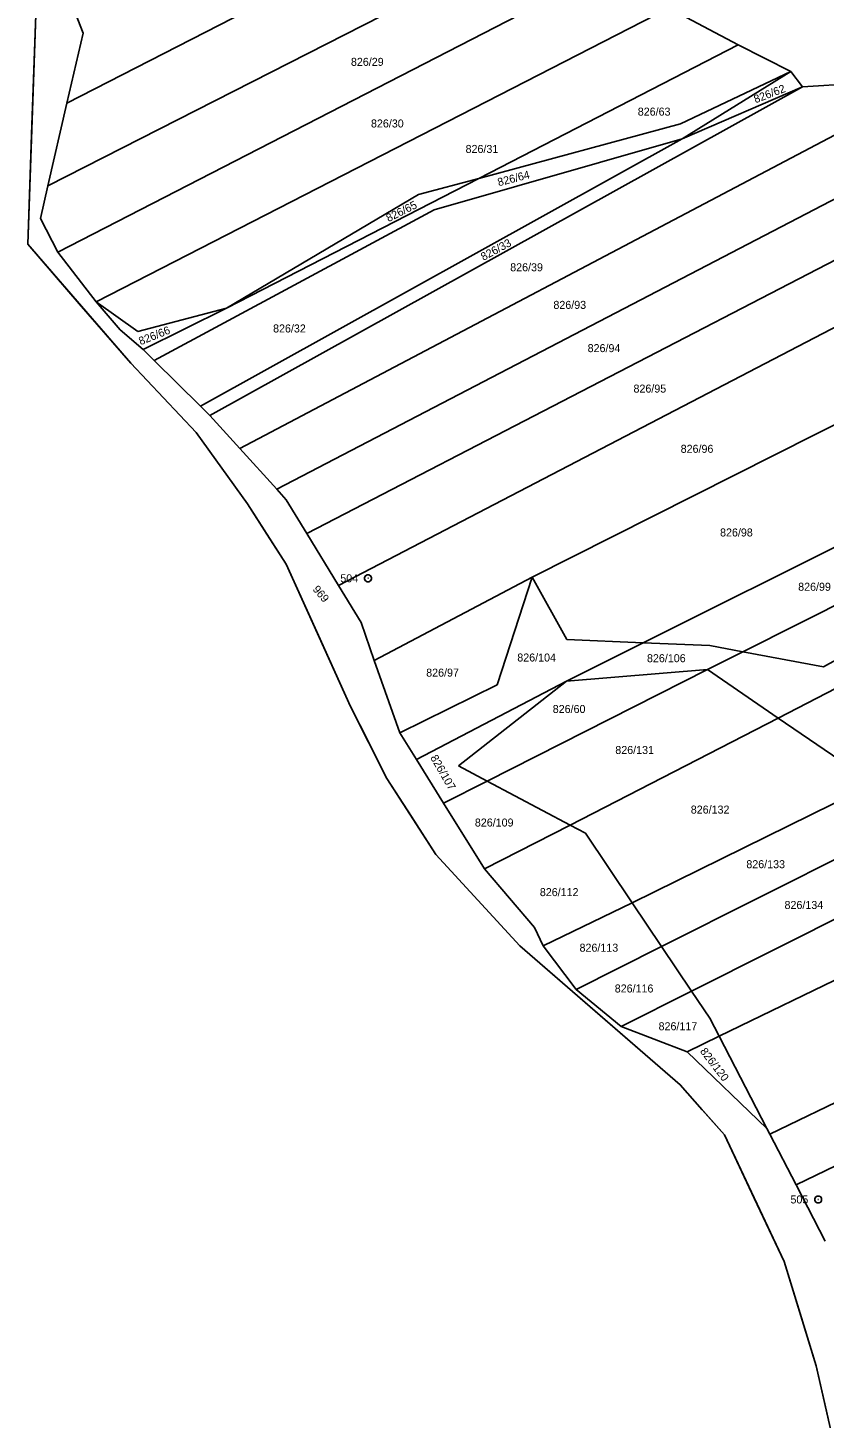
# Model space of a CAD drawing. Extents: x -593358 to -590116, y -1072518 to -1068420.
# Drawn here: x -593005 to -592835.7, y -1070925.3 to -1070630 of the extents above; entities that cross this region are included whole.
import ezdxf

# ---------------------------------------------------------------- set-up
doc = ezdxf.new("R2010")
doc.units = 0
for name, color, linetype in [('katastrální hranice', 7, 'Continuous'), ('Parcela KN', 7, 'Continuous'), ('Parcela ZE', 7, 'Continuous'), ('Parcelní číslo', 7, 'Continuous'), ('vnější obvod_šetřený', 7, 'Continuous'), ('Vrstva 17', 7, 'Continuous'), ('Vrstva 24', 7, 'Continuous')]:
    doc.layers.add(name, color=color, linetype=linetype)

msp = doc.modelspace()

# ---------------------------------------------------------------- linework, layer by layer
at = {"layer": 'katastrální hranice'}
for p, q in [((-593004.98, -1070675.93), (-593003.22, -1070625.24)), ((-592983.1, -1070701.21), (-593004.98, -1070675.93)), ((-592969.21, -1070715.93), (-592983.1, -1070701.21)), ((-592958.26, -1070731.07), (-592969.21, -1070715.93)), ((-592950.09, -1070743.91), (-592958.26, -1070731.07)), ((-592936.37, -1070774.13), (-592950.09, -1070743.91)), ((-592928.69, -1070789.39), (-592936.37, -1070774.13)), ((-592918.25, -1070805.57), (-592928.69, -1070789.39)), ((-592900.4, -1070824.95), (-592918.25, -1070805.57)), ((-592866.35, -1070854.51), (-592900.4, -1070824.95)), ((-592856.92, -1070865.09), (-592866.35, -1070854.51)), ((-592844.25, -1070892), (-592856.92, -1070865.09)), ((-592837.43, -1070914.17), (-592844.25, -1070892)), ((-592832.3, -1070936.59), (-592837.43, -1070914.17))]:
    msp.add_line(p, q, dxfattribs=at)
at = {"layer": 'Parcela KN'}
for p, q in [((-592996.65, -1070645.98), (-592883.74, -1070588.08)), ((-593000.7, -1070663.57), (-592878.48, -1070601.26)), ((-592998.58, -1070677.61), (-592873.65, -1070613.39)), ((-592993.22, -1070631.13), (-592995.33, -1070625.64)), ((-592990.46, -1070688.17), (-592868.72, -1070625.78)), ((-592868.72, -1070625.78), (-592854, -1070633.57)), ((-592993.22, -1070631.13), (-592996.65, -1070645.98)), ((-592854, -1070633.57), (-592909.16, -1070661.95)), ((-592854, -1070633.57), (-592842.82, -1070639.26)), ((-592866.26, -1070650.34), (-592842.82, -1070639.26)), ((-592842.82, -1070639.26), (-592865.95, -1070653.52)), ((-592842.82, -1070639.26), (-592840.32, -1070642.49)), ((-592840.32, -1070642.49), (-592824.4, -1070641.48)), ((-592840.32, -1070642.49), (-592966.27, -1070712.32)), ((-592865.95, -1070653.52), (-592840.32, -1070642.49)), ((-592996.65, -1070645.98), (-593000.7, -1070663.57)), ((-592909.16, -1070661.95), (-592866.26, -1070650.34)), ((-592865.95, -1070653.52), (-592968.26, -1070710.35)), ((-592865.95, -1070653.52), (-592918.61, -1070668.62)), ((-592909.16, -1070661.95), (-592962.78, -1070689.55)), ((-592921.92, -1070665.41), (-592909.16, -1070661.95)), ((-593000.7, -1070663.57), (-593002.29, -1070670.47)), ((-592962.78, -1070689.55), (-592921.92, -1070665.41)), ((-592918.61, -1070668.62), (-592978.11, -1070700.61)), ((-593002.29, -1070670.47), (-592998.58, -1070677.61)), ((-592998.58, -1070677.61), (-592990.46, -1070688.17)), ((-592990.46, -1070688.17), (-592981.59, -1070694.46)), ((-592985.38, -1070694.1), (-592990.46, -1070688.17)), ((-592981.59, -1070694.46), (-592962.78, -1070689.55)), ((-592962.78, -1070689.55), (-592980.43, -1070698.31)), ((-592980.43, -1070698.31), (-592985.38, -1070694.1)), ((-592978.11, -1070700.61), (-592980.43, -1070698.31)), ((-592968.26, -1070710.35), (-592978.11, -1070700.61)), ((-592966.27, -1070712.32), (-592968.26, -1070710.35)), ((-592959.9, -1070719.35), (-592966.27, -1070712.32)), ((-592952.08, -1070727.97), (-592959.9, -1070719.35)), ((-592950.06, -1070730.2), (-592952.08, -1070727.97)), ((-592945.68, -1070737.38), (-592950.06, -1070730.2)), ((-592938.93, -1070748.45), (-592945.68, -1070737.38)), ((-592934.16, -1070756.27), (-592938.93, -1070748.45)), ((-592897.8, -1070746.67), (-592905.23, -1070769.55)), ((-592890.45, -1070759.89), (-592897.8, -1070746.67)), ((-592810.11, -1070751.36), (-592835.85, -1070765.67)), ((-592931.34, -1070764.32), (-592934.16, -1070756.27)), ((-592874.2, -1070760.59), (-592890.45, -1070759.89)), ((-592860.04, -1070761.2), (-592874.2, -1070760.59)), ((-592852.99, -1070762.5), (-592860.04, -1070761.2)), ((-592835.85, -1070765.67), (-592852.99, -1070762.5)), ((-592925.93, -1070779.73), (-592931.34, -1070764.32)), ((-592890.47, -1070768.71), (-592913.44, -1070786.7)), ((-592860.52, -1070766.3), (-592890.47, -1070768.71)), ((-592845.5, -1070776.58), (-592860.52, -1070766.3)), ((-592905.23, -1070769.55), (-592925.93, -1070779.73)), ((-592825.15, -1070790.5), (-592845.5, -1070776.58)), ((-592925.93, -1070779.73), (-592922.4, -1070785.38)), ((-592922.4, -1070785.38), (-592916.62, -1070794.64)), ((-592913.44, -1070786.7), (-592907.33, -1070789.95)), ((-592907.33, -1070789.95), (-592889.75, -1070799.31)), ((-592916.62, -1070794.64), (-592907.89, -1070808.63)), ((-592889.75, -1070799.31), (-592886.47, -1070801.06)), ((-592886.47, -1070801.06), (-592876.55, -1070815.8)), ((-592907.89, -1070808.63), (-592897.29, -1070821.04)), ((-592876.55, -1070815.8), (-592870.28, -1070825.11)), ((-592897.29, -1070821.04), (-592895.46, -1070824.94)), ((-592895.46, -1070824.94), (-592888.41, -1070834.21)), ((-592870.28, -1070825.11), (-592863.9, -1070834.59)), ((-592888.41, -1070834.21), (-592878.89, -1070842.11)), ((-592863.9, -1070834.59), (-592860.04, -1070840.32)), ((-592878.89, -1070842.11), (-592864.83, -1070847.49)), ((-592858.04, -1070844.18), (-592860.04, -1070840.32)), ((-592847.89, -1070863.77), (-592858.04, -1070844.18)), ((-592864.83, -1070847.49), (-592847.89, -1070863.77)), ((-592847.28, -1070864.95), (-592847.89, -1070863.77)), ((-592841.69, -1070875.75), (-592847.28, -1070864.95)), ((-592835.52, -1070887.66), (-592841.69, -1070875.75))]:
    msp.add_line(p, q, dxfattribs=at)
at = {"layer": 'Parcela ZE'}
for p, q in [((-592959.9, -1070719.35), (-592832.17, -1070652.1)), ((-592952.08, -1070727.97), (-592811.32, -1070654.78)), ((-592945.68, -1070737.38), (-592808.7, -1070666.5)), ((-592938.93, -1070748.45), (-592807.39, -1070680.01)), ((-592897.8, -1070746.67), (-592808.2, -1070701.51)), ((-592845.5, -1070776.58), (-592751.39, -1070727.74)), ((-592874.2, -1070760.59), (-592809.23, -1070728.16)), ((-592852.99, -1070762.5), (-592809.7, -1070740.64)), ((-592897.8, -1070746.67), (-592931.34, -1070764.32)), ((-592890.47, -1070768.71), (-592874.2, -1070760.59)), ((-592860.52, -1070766.3), (-592852.99, -1070762.5)), ((-592890.47, -1070768.71), (-592922.4, -1070785.38)), ((-592907.33, -1070789.95), (-592860.52, -1070766.3)), ((-592889.75, -1070799.31), (-592845.5, -1070776.58)), ((-592916.62, -1070794.64), (-592907.33, -1070789.95)), ((-592825.15, -1070790.5), (-592876.55, -1070815.8)), ((-592815.08, -1070797.39), (-592870.28, -1070825.11)), ((-592907.89, -1070808.63), (-592889.75, -1070799.31)), ((-592863.9, -1070834.59), (-592804.37, -1070804.72)), ((-592858.04, -1070844.18), (-592792.97, -1070812.52)), ((-592876.55, -1070815.8), (-592895.46, -1070824.94)), ((-592870.28, -1070825.11), (-592888.41, -1070834.21)), ((-592847.28, -1070864.95), (-592770.39, -1070827.96)), ((-592878.89, -1070842.11), (-592863.9, -1070834.59)), ((-592841.69, -1070875.75), (-592759.25, -1070835.58)), ((-592864.83, -1070847.49), (-592858.04, -1070844.18))]:
    msp.add_line(p, q, dxfattribs=at)
at = {"layer": 'vnější obvod_šetřený'}
for p, q in [((-593003.22, -1070625.24), (-593004.1, -1070650.585)), ((-593004.1, -1070650.585), (-593004.98, -1070675.93)), ((-593004.98, -1070675.93), (-592994.04, -1070688.57)), ((-592994.04, -1070688.57), (-592983.1, -1070701.21)), ((-592983.1, -1070701.21), (-592976.155, -1070708.57)), ((-592976.155, -1070708.57), (-592969.21, -1070715.93)), ((-592969.21, -1070715.93), (-592963.735, -1070723.5)), ((-592963.735, -1070723.5), (-592958.26, -1070731.07)), ((-592958.26, -1070731.07), (-592954.175, -1070737.49)), ((-592954.175, -1070737.49), (-592950.09, -1070743.91)), ((-592950.09, -1070743.91), (-592943.23, -1070759.02)), ((-592943.23, -1070759.02), (-592936.37, -1070774.13)), ((-592936.37, -1070774.13), (-592932.53, -1070781.76)), ((-592932.53, -1070781.76), (-592928.69, -1070789.39)), ((-592928.69, -1070789.39), (-592923.47, -1070797.48)), ((-592923.47, -1070797.48), (-592918.25, -1070805.57)), ((-592918.25, -1070805.57), (-592909.325, -1070815.26)), ((-592909.325, -1070815.26), (-592900.4, -1070824.95)), ((-592900.4, -1070824.95), (-592883.375, -1070839.73)), ((-592883.375, -1070839.73), (-592866.35, -1070854.51)), ((-592866.35, -1070854.51), (-592861.635, -1070859.8)), ((-592861.635, -1070859.8), (-592856.92, -1070865.09)), ((-592856.92, -1070865.09), (-592850.585, -1070878.545)), ((-592850.585, -1070878.545), (-592844.25, -1070892)), ((-592844.25, -1070892), (-592840.84, -1070903.085)), ((-592840.84, -1070903.085), (-592837.43, -1070914.17)), ((-592837.43, -1070914.17), (-592834.865, -1070925.38))]:
    msp.add_line(p, q, dxfattribs=at)
at = {"layer": 'Vrstva 24'}
for p, q in [((-592932.71, -1070746.89), (-592932.61, -1070746.89)), ((-592837.05, -1070878.83), (-592836.95, -1070878.83))]:
    msp.add_line(p, q, dxfattribs=at)
for points in [[(-592932.47, -1070746.17), (-592932.13, -1070746.36), (-592931.94, -1070746.7), (-592931.94, -1070747.09), (-592932.13, -1070747.43), (-592932.47, -1070747.62), (-592932.86, -1070747.62), (-592933.2, -1070747.43), (-592933.39, -1070747.09), (-592933.39, -1070746.7), (-592933.2, -1070746.36), (-592932.86, -1070746.17)], [(-592836.81, -1070878.11), (-592836.47, -1070878.3), (-592836.28, -1070878.64), (-592836.28, -1070879.03), (-592836.47, -1070879.37), (-592836.81, -1070879.56), (-592837.2, -1070879.56), (-592837.54, -1070879.37), (-592837.73, -1070879.03), (-592837.73, -1070878.64), (-592837.54, -1070878.3), (-592837.2, -1070878.11)]]:
    msp.add_lwpolyline(points, close=True, dxfattribs=at)

# ---------------------------------------------------------------- texts
at = {"layer": 'Parcelní číslo'}
for s, p in [('826/29', (-592936.306, -1070638.05)), ('826/63', (-592875.35, -1070648.62)), ('826/30', (-592932.047, -1070651.14)), ('826/31', (-592911.942, -1070656.55)), ('826/39', (-592902.46, -1070681.68)), ('826/93', (-592893.28, -1070689.67)), ('826/32', (-592952.854, -1070694.68)), ('826/94', (-592886.003, -1070698.86)), ('826/95', (-592876.26, -1070707.45)), ('826/96', (-592866.233, -1070720.24)), ('826/98', (-592857.863, -1070738.01)), ('826/99', (-592841.263, -1070749.54)), ('826/104', (-592900.951, -1070764.57)), ('826/106', (-592873.391, -1070764.72)), ('826/97', (-592920.313, -1070767.78)), ('826/60', (-592893.42, -1070775.5)), ('826/131', (-592880.123, -1070784.21)), ('826/132', (-592864.085, -1070796.87)), ('826/109', (-592909.971, -1070799.62)), ('826/133', (-592852.278, -1070808.47)), ('826/112', (-592896.16, -1070814.4)), ('826/134', (-592844.161, -1070817.13)), ('826/113', (-592887.723, -1070826.21)), ('826/116', (-592880.246, -1070834.87)), ('826/117', (-592870.926, -1070842.89))]:
    msp.add_text(s, height=1.7, dxfattribs=at).set_placement(p)
for s, rotation, p in [('826/62', 20.85566, (-592850.305, -1070646.01)), ('826/64', 14.61043, (-592904.896, -1070663.645)), ('826/65', 26.47065, (-592928.312, -1070671.253)), ('826/33', 28.64789, (-592908.139, -1070679.498)), ('826/66', 21.65781, (-592981.005, -1070697.398)), ('969', 310.77231, (-592944.556, -1070749.31)), ('826/107', 300.0007, (-592919.505, -1070784.989)), ('826/120', 307.67834, (-592862.221, -1070847.398))]:
    msp.add_text(s, height=1.7, rotation=rotation, dxfattribs=at).set_placement(p)
at = {"layer": 'Vrstva 17'}
for s, p in [('504', (-592938.561, -1070747.74)), ('505', (-592842.901, -1070879.68))]:
    msp.add_text(s, height=1.7, dxfattribs=at).set_placement(p)

doc.saveas('drawing.dxf')
